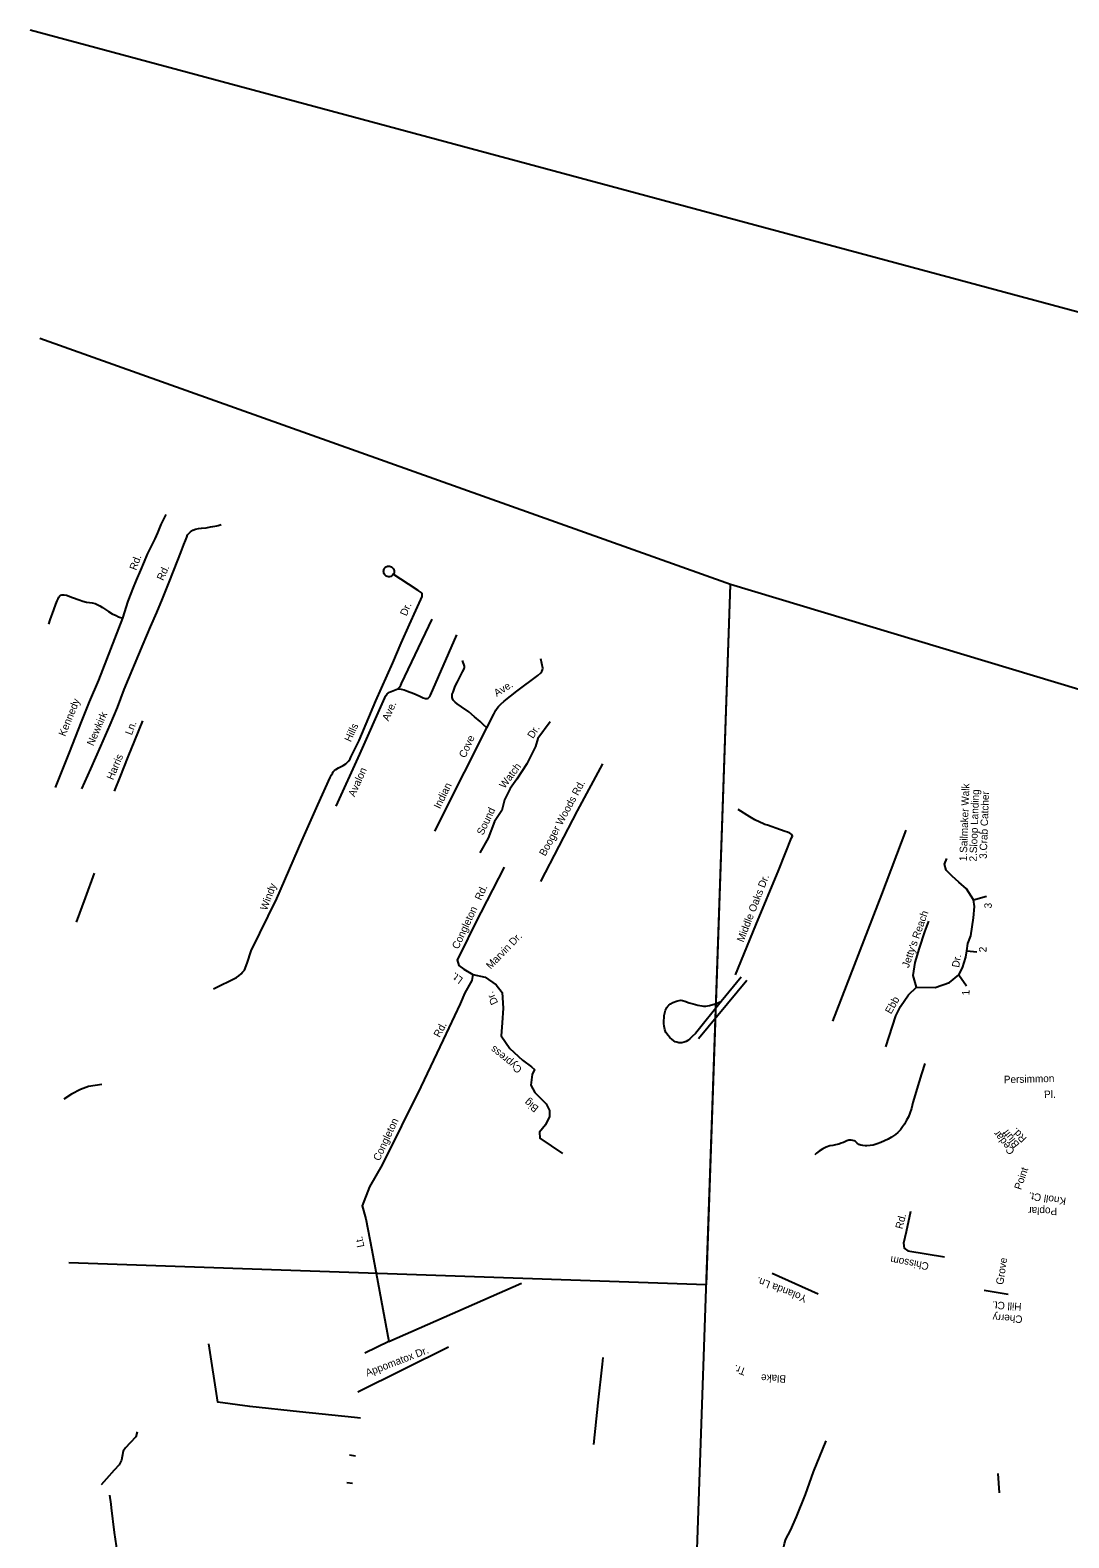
# Model space of a CAD drawing. Extents: x 2308163 to 2335412, y -96774 to 125428.
# Drawn here: x 2322026 to 2322097.3, y 82546.6 to 82650.1 of the extents above; entities that cross this region are included whole.
import ezdxf

# ---------------------------------------------------------------- set-up
doc = ezdxf.new("R2010")
doc.units = 0
for name, color, linetype in [('Old_Level_10', 7, 'Continuous'), ('Old_Level_35', 7, 'Continuous'), ('Old_Level_63', 7, 'Continuous')]:
    doc.layers.add(name, color=color, linetype=linetype)

msp = doc.modelspace()

# ---------------------------------------------------------------- linework, layer by layer
at = {"layer": 'Old_Level_35'}
for p, q in [((2322071.9, 82580.91), (2322075.22, 82584.91)), ((2322074.83, 82585.11), (2322073.46, 82583.44)), ((2322048.71, 82554.87), (2322048.29, 82554.91)), ((2322048.36, 82552.25), (2322047.96, 82552.32)), ((2322031.27, 82550.7), (2322030.91, 82550.29)), ((2322048.16, 82550.38), (2322047.76, 82550.42)), ((2322092.45, 82551.07), (2322092.54, 82549.73)), ((2322031.49, 82549.58), (2322031.57, 82548.95))]:
    msp.add_line(p, q, dxfattribs=at)
for points in [[(2322032.4, 82609.76), (2322032.76, 82610.92), (2322033.13, 82611.85), (2322033.34, 82612.36), (2322033.63, 82613.05), (2322033.88, 82613.64), (2322034.1, 82614.15), (2322034.61, 82615.2), (2322034.81, 82615.6), (2322035.03, 82616.19), (2322035.37, 82616.87)], [(2322029.58, 82598.04), (2322030.2, 82599.42), (2322030.88, 82600.97), (2322031.53, 82602.44), (2322032.04, 82603.63), (2322032.49, 82604.85), (2322033.8, 82607.97), (2322034.3, 82609.16), (2322034.72, 82610.15), (2322035.11, 82611.09), (2322035.53, 82612.11), (2322035.92, 82613.1), (2322036.37, 82614.25), (2322036.58, 82614.8), (2322036.69, 82615.08), (2322036.78, 82615.31), (2322036.84, 82615.46), (2322036.94, 82615.59), (2322037.04, 82615.68), (2322037.2, 82615.78), (2322037.39, 82615.86), (2322037.59, 82615.9), (2322037.8, 82615.93), (2322038.11, 82615.96), (2322038.42, 82616.01), (2322038.58, 82616.05), (2322038.84, 82616.09), (2322038.95, 82616.12), (2322039.15, 82616.18)], [(2322045.79, 82596.94), (2322046.62, 82598.83), (2322046.71, 82599.01), (2322046.78, 82599.1), (2322046.84, 82599.2), (2322046.92, 82599.29), (2322047.02, 82599.38), (2322047.19, 82599.48), (2322047.51, 82599.65), (2322047.7, 82599.75), (2322047.78, 82599.82), (2322047.89, 82599.93), (2322047.99, 82600.09), (2322048.04, 82600.21), (2322048.61, 82601.37), (2322049.76, 82604.08), (2322050.93, 82606.68), (2322051.51, 82608.03), (2322052.07, 82609.32), (2322052.5, 82610.27), (2322052.84, 82611.04), (2322052.93, 82611.23), (2322052.95, 82611.33), (2322052.93, 82611.44), (2322052.87, 82611.51), (2322052.66, 82611.66), (2322052.01, 82612.08), (2322050.96, 82612.77)], [(2322050.96, 82612.77), (2322050.91, 82612.71), (2322050.86, 82612.66), (2322050.79, 82612.62), (2322050.71, 82612.6), (2322050.62, 82612.6), (2322050.54, 82612.62), (2322050.48, 82612.64), (2322050.42, 82612.68), (2322050.37, 82612.73), (2322050.33, 82612.79), (2322050.31, 82612.84), (2322050.3, 82612.9), (2322050.29, 82612.97), (2322050.3, 82613.02), (2322050.31, 82613.08), (2322050.34, 82613.13), (2322050.37, 82613.19), (2322050.41, 82613.23), (2322050.46, 82613.27), (2322050.51, 82613.29), (2322050.56, 82613.31), (2322050.63, 82613.32), (2322050.7, 82613.32), (2322050.77, 82613.3), (2322050.83, 82613.28), (2322050.88, 82613.24), (2322050.91, 82613.21), (2322050.95, 82613.17), (2322050.98, 82613.13), (2322051, 82613.08), (2322051.01, 82613.03), (2322051.01, 82612.98), (2322051.01, 82612.92), (2322051.01, 82612.87), (2322050.99, 82612.82), (2322050.96, 82612.77)], [(2322027.32, 82609.34), (2322027.42, 82609.65), (2322027.66, 82610.33), (2322027.8, 82610.72), (2322027.89, 82610.95), (2322027.95, 82611.09), (2322028.01, 82611.2), (2322028.07, 82611.28), (2322028.13, 82611.32), (2322028.21, 82611.35), (2322028.27, 82611.36), (2322028.38, 82611.35), (2322028.54, 82611.32), (2322028.95, 82611.17), (2322029.41, 82611), (2322029.66, 82610.91), (2322029.91, 82610.84), (2322030.11, 82610.83), (2322030.29, 82610.8), (2322030.5, 82610.75), (2322030.64, 82610.7), (2322030.82, 82610.6), (2322031.01, 82610.48), (2322031.13, 82610.39), (2322031.41, 82610.21), (2322031.66, 82610.06), (2322031.93, 82609.93), (2322032.1, 82609.84), (2322032.4, 82609.76)], [(2322027.77, 82598.14), (2322028.73, 82600.54), (2322029.56, 82602.64), (2322030.1, 82604.01), (2322030.75, 82605.51), (2322032.4, 82609.76)], [(2322051.28, 82604.9), (2322051.38, 82605.01), (2322051.47, 82605.15), (2322051.52, 82605.26), (2322053.62, 82609.68)], [(2322051.28, 82604.9), (2322051.51, 82604.88), (2322051.7, 82604.83), (2322051.93, 82604.75), (2322052.37, 82604.58), (2322052.74, 82604.42), (2322053.02, 82604.28), (2322053.17, 82604.25), (2322053.28, 82604.24), (2322053.35, 82604.27), (2322053.4, 82604.3), (2322053.46, 82604.37), (2322053.51, 82604.46), (2322055.32, 82608.6)], [(2322057.39, 82602.22), (2322057.16, 82602.43), (2322056.92, 82602.67), (2322056.53, 82602.99), (2322056.14, 82603.32), (2322055.64, 82603.66), (2322055.34, 82603.87), (2322055.2, 82603.98), (2322055.12, 82604.08), (2322055.08, 82604.13), (2322055.02, 82604.24), (2322055, 82604.31), (2322054.99, 82604.41), (2322055.01, 82604.53), (2322055.06, 82604.67), (2322055.14, 82604.89), (2322055.21, 82605.08), (2322055.36, 82605.38), (2322055.54, 82605.75), (2322055.72, 82606.08), (2322055.82, 82606.28), (2322055.85, 82606.38), (2322055.85, 82606.47), (2322055.72, 82606.85)], [(2322057.39, 82602.22), (2322057.85, 82603.17), (2322058, 82603.44), (2322058.09, 82603.58), (2322058.19, 82603.7), (2322058.35, 82603.86), (2322058.56, 82604.06), (2322059.44, 82604.74), (2322060.87, 82605.83), (2322061.08, 82606.01), (2322061.15, 82606.1), (2322061.21, 82606.2), (2322061.23, 82606.32), (2322061.09, 82606.96)], [(2322047.05, 82596.85), (2322048.66, 82600.42), (2322050.37, 82604.29), (2322050.43, 82604.41), (2322050.46, 82604.46), (2322050.5, 82604.5), (2322050.54, 82604.55), (2322050.6, 82604.61), (2322050.63, 82604.63), (2322050.7, 82604.67), (2322051.28, 82604.9)], [(2322031.83, 82597.88), (2322032.21, 82598.84), (2322032.76, 82600.23), (2322033.22, 82601.37), (2322033.76, 82602.7)], [(2322053.81, 82595.14), (2322055.85, 82599.18), (2322057.39, 82602.22)], [(2322061.72, 82602.64), (2322060.89, 82601.49), (2322060.72, 82600.94), (2322060.13, 82599.75), (2322059.43, 82598.71), (2322058.97, 82598.06), (2322058.59, 82597.29), (2322058.41, 82596.55), (2322057.91, 82595.79), (2322057.48, 82594.66), (2322056.89, 82593.66)], [(2322061.09, 82591.69), (2322063.61, 82596.54), (2322065.35, 82599.75)], [(2322041.21, 82586.93), (2322042.96, 82590.52), (2322044.68, 82594.48), (2322045.79, 82596.94)], [(2322074.44, 82585.29), (2322075.84, 82588.68), (2322077.41, 82592.49), (2322078.3, 82594.67), (2322078.36, 82594.79), (2322078.32, 82594.9), (2322078.18, 82595.01), (2322078.02, 82595.07), (2322077.85, 82595.12), (2322077.54, 82595.23), (2322076.65, 82595.54), (2322076.47, 82595.59), (2322076.37, 82595.64), (2322076.12, 82595.75), (2322075.78, 82595.92), (2322075.44, 82596.11), (2322074.64, 82596.62)], [(2322081.12, 82582.1), (2322084.5, 82590.8), (2322086.17, 82595.2)], [(2322058.58, 82592.67), (2322056.59, 82588.8), (2322055.59, 82586.79), (2322055.35, 82586.3), (2322055.45, 82585.91), (2322055.79, 82585.67), (2322056.43, 82585.3), (2322057.27, 82585.11), (2322058.03, 82584.59), (2322058.43, 82584.07), (2322058.51, 82582.99), (2322058.44, 82581.99), (2322058.37, 82581.1), (2322058.96, 82580.23), (2322059.82, 82579.43), (2322060.44, 82578.96)], [(2322084.77, 82580.35), (2322085.46, 82582.46), (2322085.78, 82583.11), (2322086.33, 82583.9), (2322086.87, 82584.44), (2322088.14, 82584.42), (2322089.14, 82584.76), (2322089.77, 82585.27), (2322090.02, 82585.75), (2322090.25, 82586.5), (2322090.32, 82586.93), (2322090.39, 82587.42), (2322090.59, 82587.96), (2322090.77, 82589.18), (2322090.86, 82589.98), (2322090.79, 82590.42), (2322090.29, 82591.19), (2322089.78, 82591.65), (2322089.31, 82592.04), (2322088.91, 82592.46), (2322088.78, 82592.87), (2322088.94, 82593.27)], [(2322030.44, 82592.25), (2322029.82, 82590.57), (2322029.19, 82588.9)], [(2322090.79, 82590.42), (2322091.68, 82590.68)], [(2322086.87, 82584.44), (2322086.63, 82585.23), (2322086.78, 82586.12), (2322087.07, 82587.1), (2322087.43, 82588.22), (2322087.72, 82588.96)], [(2322038.62, 82584.31), (2322040.2, 82585.09), (2322040.37, 82585.22), (2322040.53, 82585.34), (2322040.62, 82585.46), (2322040.75, 82585.59), (2322040.93, 82586.09), (2322041.21, 82586.93)], [(2322090.32, 82586.93), (2322091.02, 82586.86)], [(2322056.43, 82585.3), (2322056.35, 82584.89), (2322055.86, 82584.05), (2322055.55, 82583.29), (2322054.39, 82580.81), (2322052.86, 82577.6), (2322050.19, 82572.25), (2322049.33, 82570.74), (2322048.83, 82569.43), (2322049.07, 82568.53), (2322049.49, 82566.4)], [(2322089.77, 82585.27), (2322090.31, 82584.52)], [(2322073.46, 82583.44), (2322071.69, 82581.26), (2322071.48, 82581.05), (2322071.32, 82580.9), (2322071.18, 82580.77), (2322071.07, 82580.7), (2322070.92, 82580.66), (2322070.76, 82580.62), (2322070.55, 82580.62), (2322070.41, 82580.65), (2322070.31, 82580.68), (2322070.1, 82580.84), (2322069.95, 82580.97), (2322069.82, 82581.11), (2322069.66, 82581.33), (2322069.6, 82581.52), (2322069.57, 82581.64), (2322069.56, 82581.75), (2322069.53, 82581.94), (2322069.52, 82582.14), (2322069.54, 82582.34), (2322069.56, 82582.5), (2322069.59, 82582.68), (2322069.65, 82582.85), (2322069.74, 82583.03), (2322069.8, 82583.14), (2322069.86, 82583.2), (2322069.99, 82583.29), (2322070.15, 82583.38), (2322070.4, 82583.47), (2322070.57, 82583.52), (2322070.7, 82583.55), (2322070.81, 82583.53), (2322070.97, 82583.48), (2322071.26, 82583.37), (2322071.54, 82583.28), (2322071.86, 82583.21), (2322072.13, 82583.15), (2322072.25, 82583.14), (2322072.42, 82583.14), (2322072.67, 82583.18), (2322073.04, 82583.28), (2322073.46, 82583.44)], [(2322060.44, 82578.96), (2322060.65, 82578.79), (2322060.48, 82578.44), (2322060.4, 82577.71), (2322060.67, 82577.2), (2322061.45, 82576.44), (2322061.67, 82575.97), (2322061.69, 82575.55), (2322061.4, 82574.98), (2322061, 82574.49), (2322061.02, 82574.07), (2322062.57, 82573.01)], [(2322087.43, 82579.19), (2322087.21, 82578.48), (2322087.05, 82577.97), (2322086.61, 82576.52), (2322086.52, 82576.1), (2322086.41, 82575.78), (2322086.31, 82575.53), (2322086.18, 82575.3), (2322086.04, 82575.04), (2322085.91, 82574.84), (2322085.77, 82574.65), (2322085.59, 82574.47), (2322085.42, 82574.32), (2322085.16, 82574.15), (2322084.92, 82574.01), (2322084.68, 82573.89), (2322084.43, 82573.77), (2322084.18, 82573.68), (2322083.9, 82573.6), (2322083.7, 82573.57), (2322083.46, 82573.55), (2322083.34, 82573.55), (2322083.19, 82573.56), (2322083.05, 82573.59), (2322082.99, 82573.62)], [(2322030.96, 82577.76), (2322030.05, 82577.61), (2322029.49, 82577.42), (2322028.87, 82577.1), (2322028.35, 82576.74)], [(2322082.99, 82573.62), (2322082.92, 82573.65), (2322082.79, 82573.74), (2322082.65, 82573.86), (2322082.58, 82573.9), (2322082.5, 82573.92), (2322082.38, 82573.94), (2322082.22, 82573.93), (2322082.08, 82573.88), (2322081.87, 82573.78), (2322081.71, 82573.72), (2322081.54, 82573.67), (2322081.32, 82573.62), (2322081.13, 82573.58), (2322080.93, 82573.54), (2322080.66, 82573.45), (2322080.44, 82573.34), (2322080.2, 82573.18), (2322080.01, 82573.04), (2322079.88, 82572.93)], [(2322086.45, 82569.05), (2322086.16, 82567.65), (2322085.98, 82566.87), (2322086.03, 82566.53), (2322086.27, 82566.34), (2322088.79, 82565.92)], [(2322049.49, 82566.4), (2322050.66, 82560.12), (2322049, 82559.32)], [(2322076.96, 82564.8), (2322080.13, 82563.4)], [(2322050.66, 82560.12), (2322059.76, 82564.12)], [(2322093.17, 82563.34), (2322091.51, 82563.61)], [(2322048.29, 82554.91), (2322044.53, 82555.3), (2322041.12, 82555.66), (2322038.92, 82555.95), (2322038.31, 82559.96)], [(2322048.53, 82556.67), (2322054.75, 82559.75)], [(2322065.35, 82559.03), (2322065.3, 82558.57), (2322064.99, 82555.91), (2322064.7, 82553.06)], [(2322033.38, 82553.92), (2322033.29, 82553.59), (2322032.9, 82553.17), (2322032.58, 82552.83), (2322032.42, 82552.59), (2322032.36, 82552.22), (2322032.3, 82551.97), (2322032.15, 82551.67), (2322031.8, 82551.29), (2322031.27, 82550.7)], [(2322077.75, 82545.95), (2322077.8, 82546.27), (2322077.91, 82546.55), (2322078.23, 82547.15), (2322078.64, 82548.1), (2322079.24, 82549.62), (2322079.79, 82551.18), (2322080.67, 82553.3)], [(2322031.57, 82548.95), (2322031.6, 82548.7), (2322031.81, 82547.01), (2322032.07, 82545.18), (2322032.22, 82543.97), (2322032.2, 82543.56), (2322032.05, 82543.17), (2322031.68, 82542.65), (2322031.29, 82542.26)]]:
    msp.add_lwpolyline(points, dxfattribs=at)
at = {"layer": 'Old_Level_63'}
for p, q in [((2322074.1, 82612.06), (2322026.7, 82628.94)), ((2322137.61, 82592.9), (2322074.1, 82612.06))]:
    msp.add_line(p, q, dxfattribs=at)
for points in [[(2322237.3, 82590.26), (2322216.65, 82598.81), (2322026.04, 82650.1)], [(2322074.09, 82612.05), (2322072.44, 82564.02), (2322028.7, 82565.53)], [(2322137.61, 82592.9), (2322134.07, 82490.21), (2322069.96, 82492.24), (2322074.1, 82612.06)]]:
    msp.add_lwpolyline(points, dxfattribs=at)

# ---------------------------------------------------------------- texts
at = {"layer": 'Old_Level_10'}
for s, height, rotation, p in [('Rd.', 0.513, 69.6167, (2322033.31, 82613)), ('Rd.', 0.513, 65.0847, (2322035.16, 82612.29)), ('Dr.', 0.513, 67.3169, (2322051.87, 82609.86)), ('Ave.', 0.513, 32.0499, (2322058.06, 82604.35)), ('Kennedy', 0.513, 67.8467, (2322028.44, 82601.6)), ('Newkirk', 0.513, 66.499, (2322030.37, 82600.95)), ('Ave.', 0.513, 66.0506, (2322050.63, 82602.66)), ('Ln.', 0.513, 69.1108, (2322033.01, 82601.69)), ('Hills', 0.513, 65.6411, (2322048.04, 82601.22)), ('Dr.', 0.513, 57.3171, (2322060.55, 82601.45)), ('Cove', 0.513, 65.514, (2322055.9, 82600.12)), ('Harris', 0.513, 67.3307, (2322031.73, 82598.61)), ('Avalon', 0.513, 65.8193, (2322048.3, 82597.45)), ('Watch', 0.513, 53.1139, (2322058.6, 82598.02)), ('Indian ', 0.513, 63.7995, (2322054.16, 82596.63)), ('Booger Woods Rd.', 0.5126, 61.6242, (2322061.39, 82593.38)), ('1.Sailmaker Walk', 0.5126, 88.0247, (2322090.32, 82593.07)), ('2.Sloop Landing', 0.5126, 88.0247, (2322091, 82593.05)), ('3.Crab Catcher', 0.5126, 88.0247, (2322091.69, 82593.23)), ('Sound ', 0.513, 64.3347, (2322057.12, 82594.82)), ('Middle Oaks Dr.', 0.5126, 68.7633, (2322074.99, 82587.48)), ('Windy', 0.513, 69.4786, (2322042.28, 82589.66)), ('Congleton   Rd.', 0.5126, 64.9615, (2322055.42, 82587)), ("Jetty's Reach", 0.5126, 70.5106, (2322086.33, 82585.72)), ('3', 0.513, 88.0247, (2322092.03, 82589.83)), ('Marvin Dr.', 0.513, 45.8234, (2322057.64, 82585.63)), ('Dr.', 0.513, 80.239, (2322089.79, 82585.75)), ('2', 0.513, 88.0247, (2322091.67, 82586.82)), ('Lt.', 0.513, 143.6523, (2322055.79, 82585.03)), ('Dr.', 0.513, 115.5158, (2322058.17, 82583.37)), ('Ebb ', 0.513, 60.3233, (2322085.12, 82582.55)), ('1', 0.513, 88.0247, (2322090.5, 82583.86)), ('Rd.', 0.513, 61.5377, (2322054.14, 82580.94)), ('Cypress', 0.513, 140.9663, (2322059.84, 82578.87)), ('Persimmon ', 0.513, 1.5076, (2322092.87, 82577.84)), ('Pl.', 0.513, 1.5076, (2322095.63, 82576.82)), ('Big', 0.513, 141.4721, (2322060.98, 82576.2)), ('Congleton', 0.513, 64.9413, (2322050.01, 82572.47)), ('Cedar ', 0.513, 128.3484, (2322093.65, 82573.19)), ('Bluff', 0.513, 128.3484, (2322093.97, 82573.65)), ('Rd.', 0.513, 134.7737, (2322094.47, 82574.08)), ('Point', 0.513, 71.0018, (2322094.04, 82570.49)), ('Knoll Ct.', 0.513, 171.486, (2322097.16, 82569.98)), ('Poplar', 0.513, 178.5533, (2322096.53, 82569.3)), ('Rd.', 0.513, 75.3776, (2322085.9, 82567.8)), ('Lt. ', 0.513, 101.4483, (2322048.98, 82566.63)), ('Chissom', 0.513, 169.6256, (2322087.75, 82565.51)), ('Grove ', 0.513, 81.4647, (2322092.82, 82563.99)), ('Yolanda Ln.', 0.5126, 158.6402, (2322079.4, 82563.24)), ('Hill Ct.', 0.513, 176.1975, (2322094.09, 82562.75)), ('Cherry ', 0.513, 176.1975, (2322094.16, 82561.89)), ('Appomatox Dr.', 0.5126, 20.8983, (2322049.17, 82557.71)), ('Tr.', 0.513, 159.6034, (2322075.22, 82558.25)), ('Blake', 0.513, 177.5682, (2322077.92, 82557.8))]:
    msp.add_text(s, height=height, rotation=rotation, dxfattribs=at).set_placement(p)

doc.saveas('drawing.dxf')
